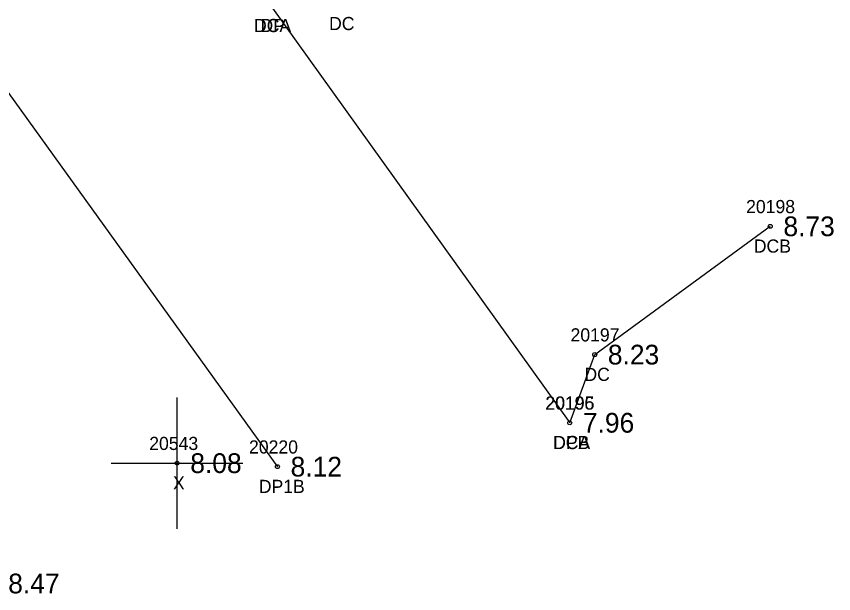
# Model space of a CAD drawing. Extents: x 2608745 to 2610333, y 641917 to 643463.
# Drawn here: x 2608960.7 to 2609022.8, y 642955.5 to 642999.4 of the extents above; entities that cross this region are included whole.
import ezdxf

# ---------------------------------------------------------------- set-up
doc = ezdxf.new("R2010")
doc.units = 0
for name, color, linetype in [('RD_EX_Conc', 7, 'Continuous'), ('RD_EX_Conc_txCode', 7, 'Continuous'), ('RD_EX_Driveway', 7, 'Continuous'), ('RD_EX_Driveway_txCode', 7, 'Continuous'), ('RD_EX_Misc', 7, 'Continuous'), ('RD_EX_Misc_txCode', 7, 'Continuous'), ('RD_EX_TX_Conc_ELEV', 7, 'Continuous'), ('RD_EX_TX_Driveway_ELEV', 7, 'Continuous'), ('RD_EX_TX_Misc_ELEV', 7, 'Continuous'), ('RD_SMD_Locator', 7, 'Continuous')]:
    doc.layers.add(name, color=color, linetype=linetype)

msp = doc.modelspace()

# ---------------------------------------------------------------- linework, layer by layer
at = {"layer": 'RD_EX_Conc'}
msp.add_lwpolyline([(2609002.723, 642968.528), (2609004.622, 642973.708), (2609017.96, 642983.46)], dxfattribs=at)
at = {"layer": 'RD_EX_Driveway'}
for points in [[(2608966.974, 643044.203), (2608964.832, 643033.445), (2608965.027, 643024.995), (2608967.043, 643017.848), (2608980.009, 643000.224), (2609002.723, 642968.528)], [(2608926.378, 643013.48), (2608937.792, 643013.459), (2608947.008, 643010.003), (2608952.733, 643003.787), (2608980.52, 642965.191)]]:
    msp.add_lwpolyline(points, dxfattribs=at)
at = {"layer": 'RD_EX_Misc'}
for p, q in [((2608972.898, 642960.458), (2608972.898, 642970.458)), ((2608967.898, 642965.458), (2608977.898, 642965.458))]:
    msp.add_line(p, q, dxfattribs=at)
at = {"layer": 'RD_SMD_Locator'}
for centre in [(2609017.96, 642983.46), (2609004.622, 642973.708), (2609002.723, 642968.528), (2609002.723, 642968.528), (2608972.898, 642965.458), (2608980.52, 642965.191)]:
    msp.add_circle(centre, 0.15, dxfattribs=at)

# ---------------------------------------------------------------- texts
at = {"layer": 'RD_EX_Conc_txCode'}
for s, p in [('DCA', (2608978.741, 642998.224)), ('DC', (2608984.442, 642998.374)), ('20198', (2609016.125, 642984.46)), ('DCB', (2609016.708, 642981.46)), ('20197', (2609002.787, 642974.708)), ('DC', (2609003.842, 642971.708)), ('20196', (2609000.865, 642969.528)), ('DCA', (2609001.456, 642966.528))]:
    msp.add_text(s, height=1, dxfattribs=at).set_placement(p)
at = {"layer": 'RD_EX_Driveway_txCode'}
for s, p in [('DP', (2608979.229, 642998.224)), ('20195', (2609000.889, 642969.528)), ('DPB', (2609001.471, 642966.528)), ('20220', (2608978.362, 642966.191)), ('DP1B', (2608979.103, 642963.191))]:
    msp.add_text(s, height=1, dxfattribs=at).set_placement(p)
at = {"layer": 'RD_EX_Misc_txCode'}
for s, p in [('20543', (2608970.78, 642966.458)), ('X', (2608972.583, 642963.458))]:
    msp.add_text(s, height=1, dxfattribs=at).set_placement(p)
at = {"layer": 'RD_EX_TX_Conc_ELEV'}
for s, p in [('8.73', (2609018.96, 642982.71)), ('8.23', (2609005.622, 642972.958)), ('7.96', (2609003.723, 642967.778)), ('8.47', (2608960.068, 642955.56))]:
    msp.add_text(s, height=1.5, dxfattribs=at).set_placement(p)
at = {"layer": 'RD_EX_TX_Driveway_ELEV'}
for s, p in [('7.96', (2609003.723, 642967.778)), ('8.12', (2608981.52, 642964.441))]:
    msp.add_text(s, height=1.5, dxfattribs=at).set_placement(p)
at = {"layer": 'RD_EX_TX_Misc_ELEV'}
msp.add_text('8.08', height=1.5, dxfattribs=at).set_placement((2608973.898, 642964.708))

doc.saveas('drawing.dxf')
